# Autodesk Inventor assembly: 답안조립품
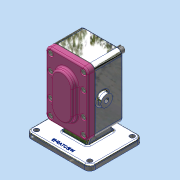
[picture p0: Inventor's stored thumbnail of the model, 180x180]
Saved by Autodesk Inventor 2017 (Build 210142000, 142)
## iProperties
Part Number: 답안조립품
Material: 일반
Document SubType Name: Assembly
Designer: MRC
Author: MRC
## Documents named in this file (11)
- C:\Users\MRC\Desktop\700407V1043\답안조립품.iam
- C:\Users\MRC\Desktop\700407V1043\본체.ipt
- C:\Users\MRC\Desktop\700407V1043\Ű 6 x 6 x 18.ipt
- C:\Users\MRC\Desktop\700407V1043\개스킷.ipt
- C:\Users\MRC\Desktop\700407V1043\메인축.ipt
- C:\Users\MRC\Desktop\700407V1043\베어링부시.ipt
- C:\Users\MRC\Desktop\700407V1043\볼트 M5.ipt
- C:\Users\MRC\Desktop\700407V1043\서브축.ipt
- C:\Users\MRC\Desktop\700407V1043\스퍼기어.ipt
- C:\Users\MRC\Desktop\700407V1043\오일 실 16 28 7.ipt
- C:\Users\MRC\Desktop\700407V1043\커버.ipt
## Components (3 placed, 2 different names)
1. Ű 6 x 6 x 18:1 — 각도:1
2. 개스킷:1
3. Ű 6 x 6 x 18:2 — 각도:2
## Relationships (2: Angle 2)
- 각도:1 [Angle]: Ű 6 x 6 x 18:1
- 각도:2 [Angle]: Ű 6 x 6 x 18:2
